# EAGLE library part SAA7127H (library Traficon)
Digital video encoder
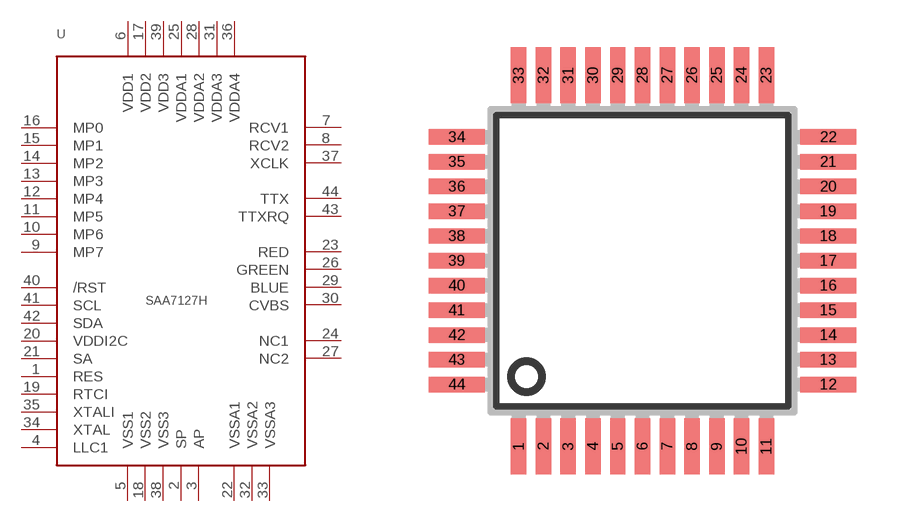
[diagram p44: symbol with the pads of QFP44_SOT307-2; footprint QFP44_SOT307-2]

Designator prefix U

## SAA7127H  [QFP44_SOT307-2]
1  RES
2  SP  pas
3  AP  pas
4  LLC1
5  VSS1  pas
6  VDD1  pas
7  RCV1
8  RCV2
9  MP7
10  MP6
11  MP5
12  MP4
13  MP3
14  MP2
15  MP1
16  MP0
17  VDD2  pas
18  VSS2  pas
19  RTCI
20  VDDI2C
21  SA
22  VSSA1  pas
23  RED
24  NC1
25  VDDA1  pas
26  GREEN
27  NC2
28  VDDA2  pas
29  BLUE
30  CVBS
31  VDDA3  pas
32  VSSA2  pas
33  VSSA3  pas
34  XTAL
35  XTALI
36  VDDA4  pas
37  XCLK
38  VSS3  pas
39  VDD3  pas
40  /RST
41  SCL
42  SDA
43  TTXRQ
44  TTX

## Footprint QFP44_SOT307-2 (pad centres in mm)
Plastic Quad Flat Package SOT307-2 44 leads (lead length 1.3 mm); body 10 x 10 x 1.75 mm SOT307-2 source: http://www.semiconductors.philips.com/ LQFP-MSQFP-QFP-SQFP-TQFP-REFLOW.pdf
smd 0.5 x 1.8: 1 -4,-6; 2 -3.2,-6; 3 -2.4,-6; 4 -1.6,-6; 5 -0.8,-6; 6 0,-6; 7 0.8,-6; 8 1.6,-6; 9 2.4,-6; 10 3.2,-6; 11 4,-6; 23 4,6; 24 3.2,6; 25 2.4,6; 26 1.6,6; 27 0.8,6; 28 0,6; 29 -0.8,6; 30 -1.6,6; 31 -2.4,6; 32 -3.2,6; 33 -4,6
smd 1.8 x 0.5: 12 6,-4; 13 6,-3.2; 14 6,-2.4; 15 6,-1.6; 16 6,-0.8; 17 6,0; 18 6,0.8; 19 6,1.6; 20 6,2.4; 21 6,3.2; 22 6,4; 34 -6,4; 35 -6,3.2; 36 -6,2.4; 37 -6,1.6; 38 -6,0.8; 39 -6,0; 40 -6,-0.8; 41 -6,-1.6; 42 -6,-2.4; 43 -6,-3.2; 44 -6,-4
